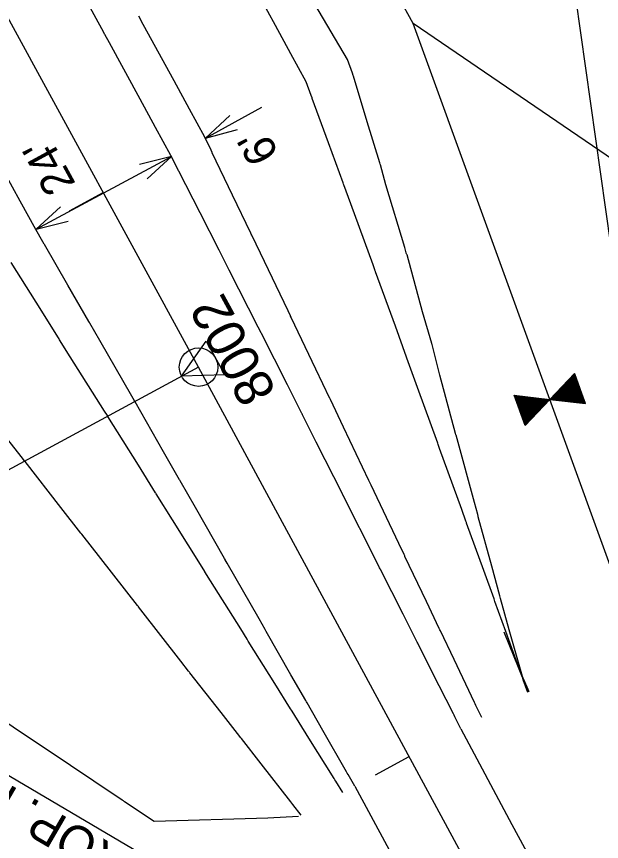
# Model space of a CAD drawing. Extents: x 1627557 to 1636561, y 783843 to 794002.
# Drawn here: x 1628208.2 to 1628299.3, y 784515.8 to 784644.3 of the extents above; entities that cross this region are included whole.
import ezdxf

# ---------------------------------------------------------------- set-up
doc = ezdxf.new("R2010")
doc.units = 0
for name, color, linetype in [('Dimensions', 7, 'Continuous'), ('GATE', 7, 'Continuous'), ('Point Numbers', 7, 'Continuous'), ('R_Clearzone', 7, 'Continuous'), ('R_Ditch', 7, 'Continuous'), ('R_Horz Alg', 7, 'Continuous'), ('R_Horz Alg Annot', 7, 'Continuous'), ('R_Proposed Const Limits', 7, 'Continuous'), ('R_Proposed Road', 7, 'Continuous'), ('R_Proposed Shoulder', 7, 'Continuous'), ('R_ROW', 7, 'Continuous'), ('R_ROW Annot', 7, 'Continuous'), ('R_ROW Annot Labels', 7, 'Continuous'), ('R_Temp Const Easement', 7, 'Continuous')]:
    doc.layers.add(name, color=color, linetype=linetype)

msp = doc.modelspace()

# ---------------------------------------------------------------- linework, layer by layer
at = {"layer": 'Dimensions'}
for p, q in [((1628237.59, 784625.39), (1628246.37, 784630.18)), ((1628237.59, 784625.39), (1628241.38, 784628.88)), ((1628237.59, 784625.39), (1628242.58, 784626.69)), ((1628211.22, 784611.19), (1628232.33, 784622.52)), ((1628232.33, 784622.52), (1628227.33, 784621.26)), ((1628232.33, 784622.52), (1628228.51, 784619.05)), ((1628211.22, 784611.19), (1628215.03, 784614.65)), ((1628211.22, 784611.19), (1628216.21, 784612.44))]:
    msp.add_line(p, q, dxfattribs=at)
at = {"layer": 'GATE'}
for p, q in [((1628294.16, 784587.72), (1628295.45, 784584.16)), ((1628294.24, 784587.8), (1628295.56, 784584.15)), ((1628294.31, 784587.88), (1628295.67, 784584.14)), ((1628294.39, 784587.96), (1628295.78, 784584.12)), ((1628294.47, 784588.05), (1628295.9, 784584.11)), ((1628294.54, 784588.13), (1628296.01, 784584.1)), ((1628294.62, 784588.21), (1628296.12, 784584.09)), ((1628294.7, 784588.29), (1628296.23, 784584.07)), ((1628294.77, 784588.37), (1628296.34, 784584.06)), ((1628294.85, 784588.45), (1628296.45, 784584.05)), ((1628294.93, 784588.53), (1628296.56, 784584.03)), ((1628295.01, 784588.61), (1628296.67, 784584.02)), ((1628295.08, 784588.69), (1628296.78, 784584.01)), ((1628292.93, 784586.42), (1628293.67, 784584.37)), ((1628293.01, 784586.5), (1628293.79, 784584.36)), ((1628293.08, 784586.59), (1628293.9, 784584.34)), ((1628293.16, 784586.67), (1628294.01, 784584.33)), ((1628293.24, 784586.75), (1628294.12, 784584.32)), ((1628293.31, 784586.83), (1628294.23, 784584.3)), ((1628293.39, 784586.91), (1628294.34, 784584.29)), ((1628293.47, 784586.99), (1628294.45, 784584.28)), ((1628293.54, 784587.07), (1628294.56, 784584.27)), ((1628293.62, 784587.15), (1628294.67, 784584.25)), ((1628293.7, 784587.23), (1628294.78, 784584.24)), ((1628293.77, 784587.32), (1628294.9, 784584.23)), ((1628293.85, 784587.4), (1628295.01, 784584.21)), ((1628293.93, 784587.48), (1628295.12, 784584.2)), ((1628294.01, 784587.56), (1628295.23, 784584.19)), ((1628294.08, 784587.64), (1628295.34, 784584.18)), ((1628285.77, 784585.28), (1628287.45, 784580.65)), ((1628285.88, 784585.27), (1628287.53, 784580.73)), ((1628286, 784585.26), (1628287.61, 784580.81)), ((1628286.11, 784585.25), (1628287.69, 784580.89)), ((1628286.22, 784585.23), (1628287.76, 784580.98)), ((1628286.33, 784585.22), (1628287.84, 784581.06)), ((1628286.44, 784585.21), (1628287.92, 784581.14)), ((1628286.55, 784585.19), (1628287.99, 784581.22)), ((1628286.66, 784585.18), (1628288.07, 784581.3)), ((1628286.77, 784585.17), (1628288.15, 784581.38)), ((1628286.88, 784585.16), (1628288.22, 784581.46)), ((1628286.99, 784585.14), (1628288.3, 784581.54)), ((1628287.11, 784585.13), (1628288.38, 784581.62)), ((1628291.7, 784585.13), (1628291.9, 784584.57)), ((1628291.77, 784585.21), (1628292.01, 784584.56)), ((1628291.85, 784585.29), (1628292.12, 784584.55)), ((1628291.93, 784585.37), (1628292.23, 784584.54)), ((1628292, 784585.45), (1628292.34, 784584.52)), ((1628292.08, 784585.53), (1628292.45, 784584.51)), ((1628292.16, 784585.61), (1628292.56, 784584.5)), ((1628292.24, 784585.69), (1628292.67, 784584.48)), ((1628292.31, 784585.77), (1628292.79, 784584.47)), ((1628292.39, 784585.86), (1628292.9, 784584.46)), ((1628292.47, 784585.94), (1628293.01, 784584.45)), ((1628292.54, 784586.02), (1628293.12, 784584.43)), ((1628292.62, 784586.1), (1628293.23, 784584.42)), ((1628292.7, 784586.18), (1628293.34, 784584.41)), ((1628292.77, 784586.26), (1628293.45, 784584.39)), ((1628292.85, 784586.34), (1628293.56, 784584.38)), ((1628287.22, 784585.12), (1628288.46, 784581.71)), ((1628287.33, 784585.1), (1628288.53, 784581.79)), ((1628287.44, 784585.09), (1628288.61, 784581.87)), ((1628287.55, 784585.08), (1628288.69, 784581.95)), ((1628287.66, 784585.07), (1628288.76, 784582.03)), ((1628287.77, 784585.05), (1628288.84, 784582.11)), ((1628287.88, 784585.04), (1628288.92, 784582.19)), ((1628287.99, 784585.03), (1628288.99, 784582.27)), ((1628288.11, 784585.01), (1628289.07, 784582.35)), ((1628288.22, 784585), (1628289.15, 784582.44)), ((1628288.33, 784584.99), (1628289.22, 784582.52)), ((1628288.44, 784584.97), (1628289.3, 784582.6)), ((1628288.55, 784584.96), (1628289.38, 784582.68)), ((1628288.66, 784584.95), (1628289.46, 784582.76)), ((1628288.77, 784584.94), (1628289.53, 784582.84)), ((1628288.88, 784584.92), (1628289.61, 784582.92)), ((1628288.99, 784584.91), (1628289.69, 784583)), ((1628289.1, 784584.9), (1628289.76, 784583.09)), ((1628289.22, 784584.88), (1628289.84, 784583.17)), ((1628289.33, 784584.87), (1628289.92, 784583.25)), ((1628289.44, 784584.86), (1628289.99, 784583.33)), ((1628289.55, 784584.85), (1628290.07, 784583.41)), ((1628289.66, 784584.83), (1628290.15, 784583.49)), ((1628289.77, 784584.82), (1628290.22, 784583.57)), ((1628289.88, 784584.81), (1628290.3, 784583.65)), ((1628289.99, 784584.79), (1628290.38, 784583.73)), ((1628290.1, 784584.78), (1628290.46, 784583.82)), ((1628290.22, 784584.77), (1628290.53, 784583.9)), ((1628290.33, 784584.76), (1628290.61, 784583.98)), ((1628290.44, 784584.74), (1628290.69, 784584.06)), ((1628290.55, 784584.73), (1628290.76, 784584.14)), ((1628290.66, 784584.72), (1628290.84, 784584.22)), ((1628290.77, 784584.7), (1628290.92, 784584.3)), ((1628290.88, 784584.69), (1628290.99, 784584.38)), ((1628290.99, 784584.68), (1628291.07, 784584.46)), ((1628291.1, 784584.67), (1628291.15, 784584.55)), ((1628291.21, 784584.65), (1628291.22, 784584.63)), ((1628291.31, 784584.72), (1628291.34, 784584.64)), ((1628291.39, 784584.8), (1628291.45, 784584.63)), ((1628291.47, 784584.88), (1628291.56, 784584.61)), ((1628291.54, 784584.96), (1628291.68, 784584.6)), ((1628291.62, 784585.04), (1628291.79, 784584.59))]:
    msp.add_line(p, q, dxfattribs=at)
for points in [[(1628295.09, 784588.71), (1628291.25, 784584.65), (1628296.8, 784584.01)], [(1628285.69, 784585.29), (1628291.25, 784584.65), (1628287.4, 784580.59)]]:
    msp.add_lwpolyline(points, close=True, dxfattribs=at)
at = {"layer": 'R_Clearzone'}
for points in [[(1628287.83, 784538.98), (1628287.12, 784540.95), (1628287.03, 784541.2), (1628286.95, 784541.42), (1628284.39, 784548.49), (1628282.7, 784553.16), (1628282.64, 784553.34), (1628282.56, 784553.56), (1628280.96, 784558), (1628278.29, 784565.38), (1628278.25, 784565.48), (1628278.17, 784565.69), (1628277.52, 784567.51), (1628274.08, 784577.02), (1628273.87, 784577.6), (1628273.86, 784577.62), (1628273.79, 784577.82), (1628270.64, 784586.53), (1628269, 784591.07), (1628268.95, 784591.21), (1628268.93, 784591.25), (1628267.2, 784596.04), (1628264.12, 784604.54), (1628264.1, 784604.6), (1628264.01, 784604.8), (1628264, 784604.85), (1628263.71, 784605.63), (1628260.24, 784615.13), (1628259.16, 784618.09), (1628259.11, 784618.22), (1628259.04, 784618.42), (1628256.77, 784624.63), (1628254.24, 784631.54), (1628254.21, 784631.63), (1628254.08, 784631.99), (1628253.3, 784634.13), (1628250.9, 784638.52), (1628248.51, 784642.91), (1628243.72, 784651.69)], [(1628252.5, 784519.87), (1628251.21, 784521.52), (1628251.05, 784521.73), (1628250.9, 784521.92), (1628246.26, 784527.86), (1628243.2, 784531.79), (1628243.08, 784531.94), (1628242.94, 784532.12), (1628240.03, 784535.86), (1628235.18, 784542.06), (1628235.12, 784542.15), (1628234.98, 784542.32), (1628233.79, 784543.85), (1628227.55, 784551.85), (1628227.17, 784552.33), (1628227.15, 784552.35), (1628227.02, 784552.52), (1628221.31, 784559.84), (1628218.33, 784563.66), (1628218.24, 784563.77), (1628218.21, 784563.81), (1628215.07, 784567.83), (1628209.49, 784574.99), (1628209.45, 784575.04), (1628209.43, 784575.04), (1628209.4, 784575.08), (1628208.88, 784575.74), (1628202.61, 784583.71)]]:
    msp.add_lwpolyline(points, dxfattribs=at)
at = {"layer": 'R_Ditch'}
for points in [[(1628284.39, 784548.49), (1628282.7, 784553.16), (1628282.64, 784553.34), (1628282.56, 784553.56), (1628280.96, 784558), (1628278.29, 784565.38), (1628278.25, 784565.48), (1628278.17, 784565.69), (1628277.52, 784567.51), (1628274.08, 784577.02), (1628273.87, 784577.6), (1628273.86, 784577.62), (1628273.79, 784577.82), (1628270.64, 784586.53), (1628269, 784591.07), (1628268.95, 784591.21), (1628268.93, 784591.25), (1628267.2, 784596.04), (1628264.12, 784604.54), (1628264.1, 784604.6), (1628264.01, 784604.8), (1628264, 784604.85), (1628263.71, 784605.63), (1628260.24, 784615.13), (1628259.16, 784618.09), (1628259.11, 784618.22), (1628259.04, 784618.42), (1628256.77, 784624.63), (1628254.24, 784631.54), (1628254.21, 784631.63), (1628254.08, 784631.99), (1628253.3, 784634.13), (1628250.91, 784638.52), (1628248.51, 784642.91), (1628243.75, 784651.7)], [(1628251.21, 784521.52), (1628251.05, 784521.73), (1628250.9, 784521.92), (1628246.26, 784527.86), (1628243.2, 784531.79), (1628243.08, 784531.94), (1628242.94, 784532.12), (1628240.03, 784535.86), (1628235.18, 784542.06), (1628235.12, 784542.15), (1628234.98, 784542.32), (1628233.79, 784543.85), (1628227.55, 784551.85), (1628227.17, 784552.33), (1628227.15, 784552.35), (1628227.02, 784552.52), (1628221.31, 784559.84), (1628218.33, 784563.66), (1628218.24, 784563.77), (1628218.21, 784563.81), (1628215.07, 784567.83), (1628209.49, 784574.99), (1628209.45, 784575.04), (1628209.43, 784575.04), (1628209.4, 784575.08), (1628208.88, 784575.74), (1628202.61, 784583.71)]]:
    msp.add_lwpolyline(points, dxfattribs=at)
at = {"layer": 'R_Horz Alg'}
for p, q in [((1628236.53, 784589.68), (1627810.31, 785371.39)), ((1628609.13, 783900.95), (1628236.53, 784589.68))]:
    msp.add_line(p, q, dxfattribs=at)
msp.add_circle((1628236.53, 784589.68), 3, dxfattribs=at)
at = {"layer": 'R_Horz Alg Annot'}
for points in [[(1628216.42, 784614.02), (1628221.69, 784616.89)], [(1628236.53, 784589.68), (1628073.18, 784501.32)], [(1628264.09, 784526.13), (1628269.36, 784528.99)]]:
    msp.add_lwpolyline(points, dxfattribs=at)
msp.add_lwpolyline([(1628233.89, 784588.25), (1628237.73, 784593.75), (1628240.6, 784588.48)], close=True, dxfattribs=at)
at = {"layer": 'R_Proposed Const Limits'}
for points in [[(1628286.99, 784541.45), (1628284.9, 784548.76), (1628283.57, 784553.63), (1628283.52, 784553.82), (1628283.46, 784554.04), (1628282.21, 784558.68), (1628280.11, 784566.37), (1628280.09, 784566.47), (1628280.03, 784566.69), (1628279.51, 784568.59), (1628276.81, 784578.5), (1628276.64, 784579.1), (1628276.63, 784579.12), (1628276.57, 784579.33), (1628274.13, 784588.42), (1628272.91, 784593.19), (1628272.87, 784593.33), (1628272.85, 784593.38), (1628271.42, 784598.32), (1628269.02, 784607.19), (1628269, 784607.25), (1628268.89, 784607.46), (1628268.88, 784607.51), (1628268.64, 784608.32), (1628265.71, 784618.11), (1628264.87, 784621.2), (1628264.83, 784621.33), (1628264.76, 784621.54), (1628262.82, 784627.93), (1628260.66, 784635.04), (1628260.63, 784635.13), (1628260.52, 784635.5), (1628259.75, 784637.65), (1628257.19, 784641.95), (1628254.64, 784646.25)], [(1628287.95, 784539.04), (1628284.16, 784548.36)], [(1628288.04, 784539.09), (1628287.2, 784540.99), (1628287.09, 784541.23), (1628286.99, 784541.45)], [(1628252.12, 784519.66), (1628247.31, 784519.41), (1628229.62, 784518.85), (1628225.01, 784521.95), (1628224.83, 784522.07), (1628224.62, 784522.21), (1628220.22, 784525.14), (1628212.93, 784530.03), (1628212.83, 784530.09), (1628212.63, 784530.23), (1628210.81, 784531.42), (1628201.4, 784537.7)]]:
    msp.add_lwpolyline(points, dxfattribs=at)
at = {"layer": 'R_Proposed Road'}
for points in [[(1628277.39, 784533.33), (1628276.46, 784535.18), (1628276.34, 784535.42), (1628276.24, 784535.63), (1628272.89, 784542.27), (1628270.67, 784546.66), (1628270.59, 784546.82), (1628270.49, 784547.02), (1628268.38, 784551.2), (1628264.88, 784558.13), (1628264.84, 784558.23), (1628264.74, 784558.42), (1628263.88, 784560.13), (1628259.37, 784569.06), (1628259.1, 784569.61), (1628259.08, 784569.63), (1628258.99, 784569.82), (1628254.86, 784577.99), (1628252.71, 784582.26), (1628252.65, 784582.39), (1628252.63, 784582.43), (1628250.36, 784586.92), (1628246.33, 784594.91), (1628246.3, 784594.97), (1628246.23, 784595.11), (1628246.21, 784595.15), (1628245.83, 784595.89), (1628241.3, 784604.8), (1628239.89, 784607.58), (1628239.82, 784607.7), (1628239.73, 784607.89), (1628236.76, 784613.72), (1628233.46, 784620.21), (1628233.42, 784620.29), (1628233.25, 784620.63), (1628232.23, 784622.64), (1628229.83, 784627.03), (1628227.44, 784631.42), (1628222.65, 784640.2), (1628221.95, 784641.5), (1628221.9, 784641.58), (1628221.76, 784641.84), (1628217.87, 784648.98)], [(1628260.85, 784524.38), (1628259.82, 784526.18), (1628259.69, 784526.41), (1628259.57, 784526.61), (1628255.89, 784533.07), (1628253.45, 784537.34), (1628253.36, 784537.5), (1628253.24, 784537.7), (1628250.92, 784541.75), (1628247.07, 784548.49), (1628247.02, 784548.59), (1628246.91, 784548.78), (1628245.96, 784550.44), (1628241, 784559.12), (1628240.7, 784559.65), (1628240.68, 784559.68), (1628240.58, 784559.86), (1628236.04, 784567.81), (1628233.67, 784571.96), (1628233.6, 784572.08), (1628233.57, 784572.12), (1628231.08, 784576.49), (1628226.64, 784584.26), (1628226.6, 784584.32), (1628226.56, 784584.38), (1628226.54, 784584.43), (1628226.13, 784585.14), (1628221.14, 784593.81), (1628219.58, 784596.51), (1628219.52, 784596.63), (1628219.41, 784596.81), (1628216.15, 784602.48), (1628212.51, 784608.79), (1628212.47, 784608.87), (1628212.28, 784609.2), (1628211.16, 784611.15), (1628208.76, 784615.54), (1628206.37, 784619.93)], [(1628277.39, 784533.33), (1628285.34, 784518.42), (1628300.76, 784489.98), (1628316.28, 784461.44), (1628335.06, 784427), (1628349.33, 784401.01)], [(1628260.85, 784524.38), (1628278.3, 784492), (1628300.03, 784451.73), (1628318.43, 784417.75), (1628332.47, 784391.89)]]:
    msp.add_lwpolyline(points, dxfattribs=at)
at = {"layer": 'R_Proposed Shoulder'}
for points in [[(1628280.64, 784535.09), (1628279.75, 784536.96), (1628279.63, 784537.2), (1628279.53, 784537.41), (1628276.34, 784544.13), (1628274.22, 784548.57), (1628274.14, 784548.74), (1628274.04, 784548.95), (1628272.03, 784553.17), (1628268.69, 784560.19), (1628268.65, 784560.29), (1628268.55, 784560.49), (1628267.73, 784562.21), (1628263.43, 784571.26), (1628263.17, 784571.81), (1628263.15, 784571.83), (1628263.06, 784572.02), (1628259.13, 784580.3), (1628257.07, 784584.62), (1628257.01, 784584.75), (1628256.99, 784584.79), (1628254.82, 784589.34), (1628250.97, 784597.43), (1628250.95, 784597.49), (1628250.87, 784597.64), (1628250.85, 784597.68), (1628250.49, 784598.43), (1628246.16, 784607.46), (1628244.81, 784610.27), (1628244.75, 784610.39), (1628244.66, 784610.58), (1628241.83, 784616.48), (1628238.67, 784623.06), (1628238.63, 784623.14), (1628238.47, 784623.48), (1628237.49, 784625.51), (1628235.1, 784629.9), (1628232.71, 784634.29), (1628227.92, 784643.07), (1628227.21, 784644.37)], [(1628259, 784523.38), (1628257.91, 784525.14), (1628257.76, 784525.37), (1628257.64, 784525.57), (1628253.7, 784531.88), (1628251.09, 784536.06), (1628250.99, 784536.22), (1628250.87, 784536.41), (1628248.39, 784540.38), (1628244.27, 784546.98), (1628244.22, 784547.07), (1628244.1, 784547.26), (1628243.09, 784548.88), (1628237.78, 784557.38), (1628237.46, 784557.9), (1628237.44, 784557.92), (1628237.33, 784558.1), (1628232.48, 784565.88), (1628229.94, 784569.94), (1628229.86, 784570.06), (1628229.84, 784570.1), (1628227.17, 784574.38), (1628222.42, 784581.98), (1628222.39, 784582.04), (1628222.35, 784582.09), (1628222.33, 784582.13), (1628221.89, 784582.83), (1628216.55, 784591.31), (1628214.89, 784593.95), (1628214.82, 784594.07), (1628214.71, 784594.25), (1628211.22, 784599.8), (1628207.34, 784605.97)]]:
    msp.add_lwpolyline(points, dxfattribs=at)
at = {"layer": 'R_ROW'}
for p, q in [((1628269.98, 784643.22), (1628198.17, 784774.92)), ((1628304.54, 784548.02), (1628269.98, 784643.22)), ((1628234.18, 784509.96), (1628133.89, 784569.02))]:
    msp.add_line(p, q, dxfattribs=at)
at = {"layer": 'R_ROW Annot'}
msp.add_line((1628314.94, 784612.53), (1628269.98, 784643.22), dxfattribs=at)
at = {"layer": 'R_Temp Const Easement'}
msp.add_line((1628308.94, 784550.4), (1628279.18, 784762.14), dxfattribs=at)

# ---------------------------------------------------------------- texts
at = {"layer": 'Dimensions'}
for s, p in [("6'", (1628249.16, 784622.91)), ("24'", (1628217.46, 784618.23))]:
    msp.add_text(s, height=5, rotation=118.601, dxfattribs=at).set_placement(p)
at = {"layer": 'Point Numbers'}
msp.add_text('8002', height=6, rotation=118.64, dxfattribs=at).set_placement((1628248.77, 784585.88))
at = {"layer": 'R_ROW Annot Labels'}
msp.add_text('PROP. ROW', height=5.5, rotation=149.9112, dxfattribs=at).set_placement((1628230.21, 784511.29))

doc.saveas('drawing.dxf')
